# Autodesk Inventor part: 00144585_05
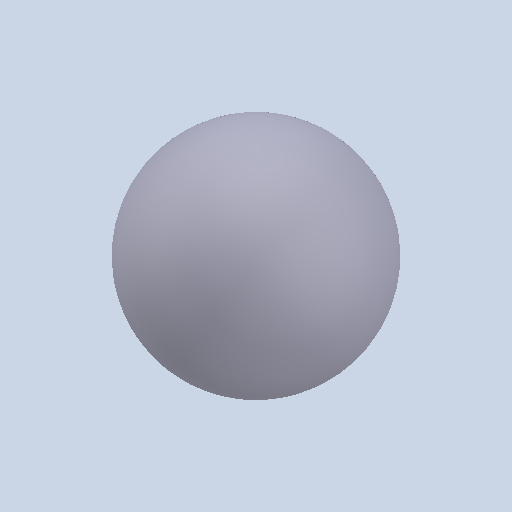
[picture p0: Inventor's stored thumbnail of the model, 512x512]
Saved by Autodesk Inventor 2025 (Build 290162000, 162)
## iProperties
Created: 2021-02
Part Number: 00144585_05
Material: Generico
Document SubType Name: Modeling
Designer: Ryzen5700u
Density: 1 g/cm^3
Appearance: Default
Author: Ryzen5700u
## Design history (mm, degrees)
feature "Solido1"
node "Solido2"
